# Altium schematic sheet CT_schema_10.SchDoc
size 147 x 119 mm
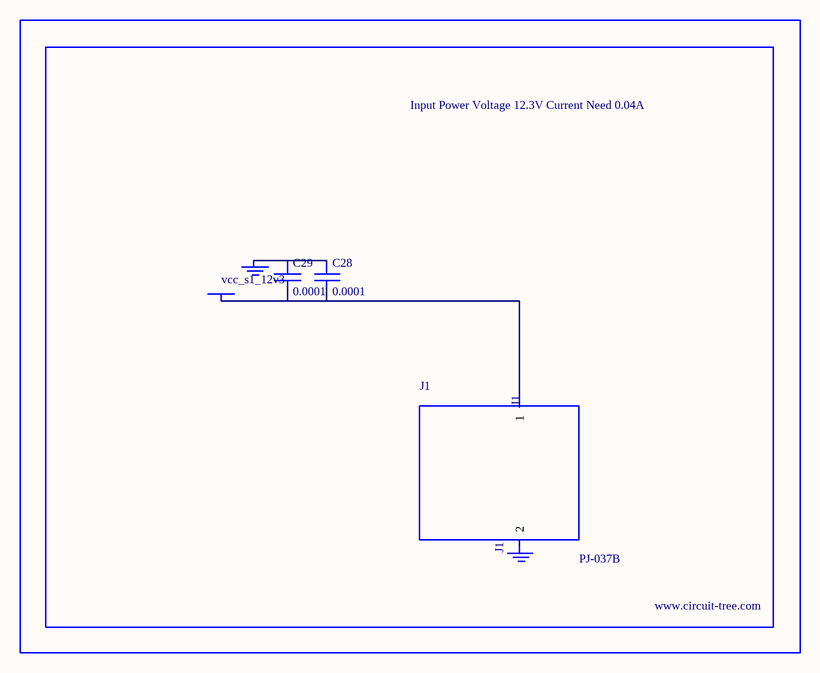
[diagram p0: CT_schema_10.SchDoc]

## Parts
BORDER9  (no value)
C28  0.0001  [EXV-9H]
C29  0.0001  [EXV-9H]
GND_INSTANCE_9_0  (no value)
GND_INSTANCE_9_1  (no value)
J1  PJ-037B  [PJ-037B_PACKAGE]
POWER_INSTANCE_9_0  vcc_s1_12v3

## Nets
NetC28_1: C28.1 C29.1 GND_INSTANCE_9_0.0(GND)
NetC28_2: C28.2 C29.2 J1.1 POWER_INSTANCE_9_0.0(PWR)

Not connected (* = marked no-connect by the designer): GND_INSTANCE_9_1 0(GND); J1 2

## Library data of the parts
BORDER9 = BORDER_PAGE9
C28 C29 = EDK107M035A9HAA
GND_INSTANCE_9_0 GND_INSTANCE_9_1 = GND
POWER_INSTANCE_9_0 = PWR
